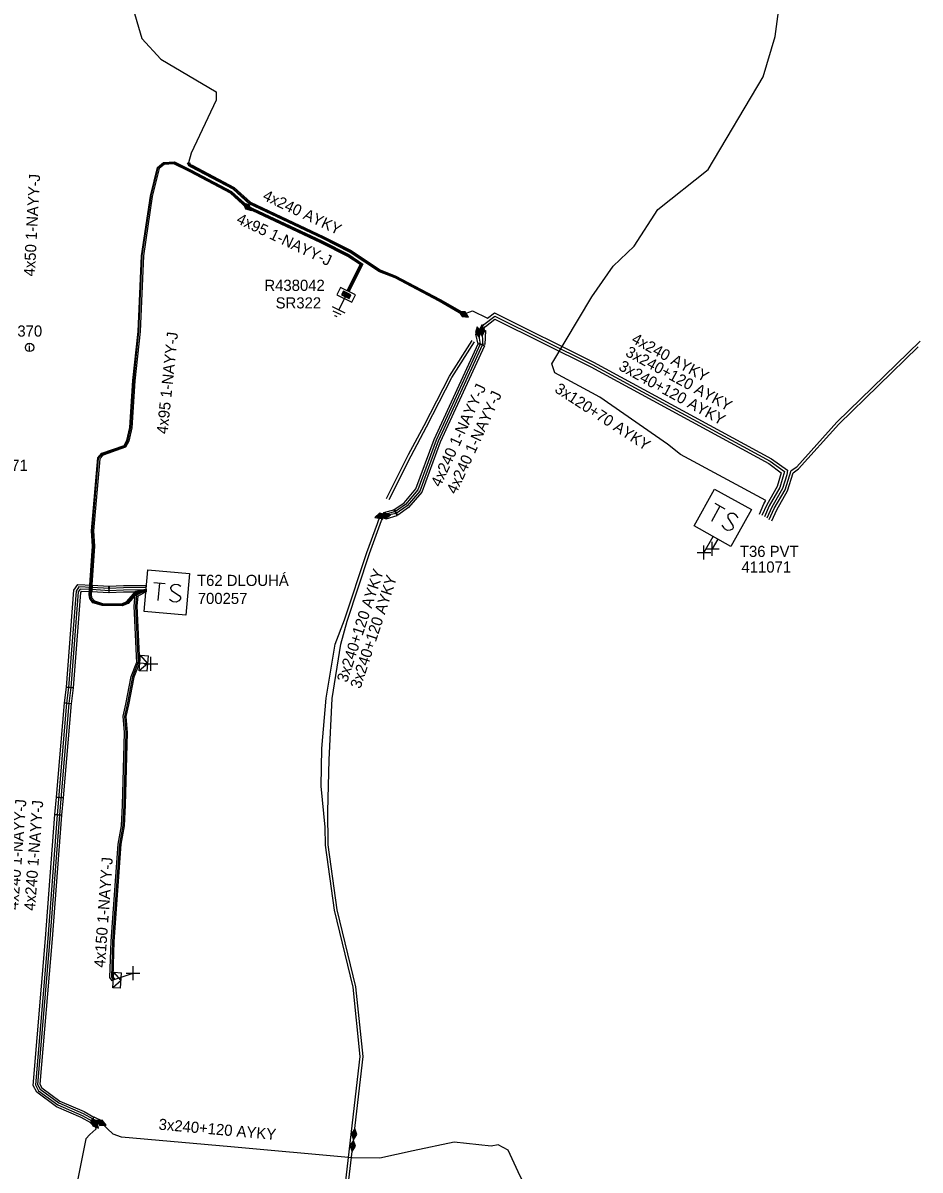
# Model space of a CAD drawing. Extents: x -540466 to -537383, y -1184038 to -1179972.
# Drawn here: x -537936.6 to -537856, y -1180822.8 to -1180719.7 of the extents above; entities that cross this region are included whole.
import ezdxf

# ---------------------------------------------------------------- set-up
doc = ezdxf.new("R2010")
doc.units = 0
for name, color, linetype in [('Vrstva 1', 7, 'Continuous'), ('Vrstva 10', 7, 'Continuous'), ('Vrstva 14', 7, 'Continuous'), ('Vrstva 15', 7, 'Continuous'), ('Vrstva 19', 7, 'Continuous'), ('Vrstva 20', 7, 'Continuous'), ('Vrstva 25', 7, 'Continuous'), ('Vrstva 26', 7, 'Continuous'), ('Vrstva 27', 7, 'Continuous'), ('Vrstva 28', 7, 'Continuous'), ('Vrstva 29', 7, 'Continuous'), ('Vrstva 30', 7, 'Continuous'), ('Vrstva 31', 7, 'Continuous'), ('Vrstva 34', 7, 'Continuous'), ('Vrstva 36', 7, 'Continuous'), ('Vrstva 4', 7, 'Continuous'), ('Vrstva 5', 7, 'Continuous'), ('Vrstva 59', 7, 'Continuous'), ('Vrstva 6', 7, 'Continuous'), ('Vrstva 8', 7, 'Continuous'), ('Vrstva 9', 7, 'Continuous')]:
    doc.layers.add(name, color=color, linetype=linetype)

# ---------------------------------------------------------------- blocks, each defined once
blk = doc.blocks.new('NN770')
at = {"layer": 'Vrstva 10'}
for p, q in [((0, 0.19), (0, 0.26)), ((0, -0.28), (0, 0.11))]:
    blk.add_line(p, q, dxfattribs=at)
blk.add_circle((0, -0.01), 0.375, dxfattribs=at)
blk = doc.blocks.new('NN870')
at = {"layer": 'Vrstva 4'}
for points in [[(0, -0.25), (0.5, 0), (0, 0.25), (-0.5, 0), (0, -0.25)], [(0.37, 0), (0, 0.19), (-0.36, 0), (0, -0.19), (0.37, 0)], [(0.24, 0), (0, 0.12), (-0.25, 0), (0, -0.12), (0.24, 0)], [(0.12, 0), (0, 0.06), (-0.13, 0), (0, -0.06), (0.12, 0)]]:
    blk.add_lwpolyline(points, dxfattribs=at)
blk = doc.blocks.new('NN800')
at = {"layer": 'Vrstva 1'}
for points in [[(-0.44, 0.44), (0.44, -0.44)], [(-0.44, -0.44), (0.44, 0.44)]]:
    blk.add_lwpolyline(points, dxfattribs=at)
blk = doc.blocks.new('NN620')
at = {"layer": 'Vrstva 8'}
for points in [[(0.75, 0), (-0.75, 0)], [(-0.75, 0), (-0.75, -0.75)], [(0.75, -0.75), (0.75, 0)], [(-0.75, -0.75), (0.75, -0.75)], [(0.37, -0.18), (-0.38, -0.18)], [(-0.38, -0.18), (-0.38, -0.56)], [(-0.38, -0.56), (0.37, -0.56)], [(0.32, -0.23), (-0.33, -0.23)], [(-0.33, -0.23), (-0.33, -0.51)], [(-0.33, -0.51), (0.32, -0.51)], [(0.27, -0.27), (-0.28, -0.27)], [(-0.28, -0.27), (-0.28, -0.46)], [(-0.28, -0.46), (0.27, -0.46)], [(0.23, -0.32), (-0.23, -0.32)], [(-0.23, -0.32), (-0.23, -0.42)], [(-0.23, -0.42), (0.23, -0.42)], [(-0.19, -0.37), (0.19, -0.37)], [(0.23, -0.42), (0.23, -0.32)], [(0.27, -0.46), (0.27, -0.27)], [(0.32, -0.51), (0.32, -0.23)], [(0.37, -0.56), (0.37, -0.18)]]:
    blk.add_lwpolyline(points, dxfattribs=at)
blk = doc.blocks.new('NN630')
at = {"layer": 'Vrstva 9'}
for points in [[(0, -0.7), (-0.7, 0)], [(-0.7, -0.7), (-0.7, 0), (0.7, 0), (0.7, -0.7)], [(-0.7, -0.7), (0.7, -0.7)], [(0, -0.7), (0.7, 0)]]:
    blk.add_lwpolyline(points, dxfattribs=at)
blk = doc.blocks.new('NN810')
at = {"layer": 'Vrstva 14'}
for points in [[(0, -0.64), (0, -1.89)], [(0.63, -1.89), (-0.62, -1.89)], [(0.39, -2.2), (-0.4, -2.2)], [(0, -2.52), (-0.12, -2.52)], [(0.14, -2.52), (0, -2.52)]]:
    blk.add_lwpolyline(points, dxfattribs=at)
blk = doc.blocks.new('NN640')
at = {"layer": 'Vrstva 6'}
for points in [[(-1.89, 1.89), (1.89, 1.89)], [(-1.89, -1.89), (-1.89, 1.89)], [(1.89, 1.89), (1.89, -1.89)], [(-1.26, 0.79), (-0.22, 0.79)], [(-0.73, 0.79), (-0.73, -0.79)], [(1.2, 0.66), (0.94, 0.79), (0.66, 0.79), (0.41, 0.66), (0.28, 0.47), (0.28, 0.41), (0.41, 0.22), (1.13, -0.16), (1.26, -0.32), (1.26, -0.47), (1.13, -0.66), (0.91, -0.79), (0.63, -0.79), (0.5, -0.73), (0.28, -0.6)], [(1.89, -1.89), (-1.89, -1.89)]]:
    blk.add_lwpolyline(points, dxfattribs=at)

msp = doc.modelspace()

# ---------------------------------------------------------------- linework, layer by layer
at = {"layer": 'Vrstva 20'}
for points in [[(-537925.96, -1180740.62), (-537925.15, -1180735.25), (-537924.51, -1180732.69), (-537923.97, -1180732.24), (-537922.99, -1180732.18), (-537921.66, -1180732.83), (-537921.74, -1180733), (-537923.03, -1180732.36), (-537923.9, -1180732.41), (-537924.35, -1180732.79), (-537924.98, -1180735.29), (-537925.78, -1180740.64), (-537926.08, -1180747.43), (-537926.54, -1180751.86), (-537926.82, -1180756.08), (-537927.09, -1180757.29), (-537927.4, -1180757.82), (-537927.52, -1180757.67), (-537927.26, -1180757.22), (-537927, -1180756.06), (-537926.72, -1180751.85), (-537926.26, -1180747.42)], [(-537921.4, -1180732.49), (-537917.62, -1180734.5), (-537916.16, -1180735.8), (-537909.56, -1180738.91), (-537907.11, -1180740.16), (-537904.48, -1180741.9), (-537903.07, -1180742.46), (-537899.09, -1180744.55), (-537896.94, -1180745.79), (-537897.03, -1180745.95), (-537899.18, -1180744.71), (-537903.15, -1180742.62), (-537904.56, -1180742.06), (-537907.2, -1180740.32), (-537909.64, -1180739.07), (-537916.26, -1180735.95), (-537917.72, -1180734.65), (-537921.48, -1180732.65), (-537921.7, -1180732.55), (-537921.81, -1180732.3), (-537921.63, -1180732.24), (-537921.56, -1180732.42)], [(-537921.74, -1180733), (-537921.66, -1180732.83), (-537921.55, -1180732.89), (-537921.49, -1180732.92), (-537917.86, -1180734.85), (-537916.4, -1180736.15), (-537909.74, -1180739.29), (-537907.32, -1180740.52), (-537906.04, -1180741.37), (-537906.29, -1180741.42), (-537907.41, -1180740.68), (-537909.82, -1180739.45), (-537916.5, -1180736.3), (-537917.96, -1180735), (-537921.58, -1180733.08)], [(-537907.29, -1180743.84), (-537907.47, -1180743.76), (-537906.29, -1180741.42), (-537906.04, -1180741.37)], [(-537895.03, -1180747.35), (-537895.09, -1180748.6), (-537895.69, -1180748.58), (-537895.89, -1180747.67), (-537895.53, -1180747.33)], [(-537895.12, -1180748.72), (-537899.09, -1180757.39), (-537900.76, -1180761.88), (-537901.94, -1180763.27), (-537902.91, -1180763.96), (-537903.25, -1180763.48), (-537902.34, -1180762.83), (-537901.28, -1180761.58), (-537899.64, -1180757.14), (-537895.66, -1180748.47)], [(-537927.4, -1180757.82), (-537929.41, -1180758.54), (-537929.51, -1180758.38), (-537927.52, -1180757.67)], [(-537929.71, -1180758.88), (-537930.25, -1180765.36), (-537930.17, -1180766.74), (-537930.47, -1180771.09), (-537930.43, -1180771.36), (-537930.19, -1180771.65), (-537930.31, -1180771.83), (-537930.6, -1180771.43), (-537930.65, -1180771.1), (-537930.35, -1180766.74), (-537930.43, -1180765.36), (-537929.88, -1180758.8), (-537929.51, -1180758.38), (-537929.41, -1180758.54)], [(-537903.97, -1180764.3), (-537904.15, -1180763.72), (-537903.17, -1180763.43), (-537902.99, -1180764.01)], [(-537932.1, -1180779.46), (-537932.7, -1180779.42), (-537932.02, -1180770.7), (-537931.67, -1180770.18), (-537930.39, -1180770.24), (-537930.41, -1180770.84), (-537931.37, -1180770.8), (-537931.44, -1180770.9)], [(-537930.42, -1180770.84), (-537930.38, -1180770.24), (-537928.85, -1180770.34), (-537928.89, -1180770.94)], [(-537929.49, -1180772.08), (-537929.45, -1180771.88), (-537927.73, -1180771.91), (-537927.28, -1180771.72), (-537926.45, -1180770.77), (-537925.59, -1180770.6), (-537925.54, -1180770.6), (-537925.54, -1180770.8), (-537925.57, -1180770.8), (-537926.35, -1180770.95), (-537927.16, -1180771.88), (-537927.69, -1180772.11)], [(-537925.57, -1180770.86), (-537927.56, -1180770.88), (-537928.86, -1180770.94), (-537928.88, -1180770.34), (-537927.57, -1180770.28), (-537925.57, -1180770.26)], [(-537926.14, -1180777.21), (-537926.38, -1180777.22), (-537926.61, -1180772.12), (-537926.53, -1180771.07), (-537925.65, -1180770.63), (-537925.53, -1180770.85), (-537926.29, -1180771.23), (-537926.37, -1180772.11)], [(-537929.45, -1180771.88), (-537929.49, -1180772.08), (-537930.31, -1180771.83), (-537930.19, -1180771.65)], [(-537927.48, -1180783.49), (-537927.61, -1180782.03), (-537927.36, -1180780.95), (-537926.88, -1180778.44), (-537926.38, -1180777.16), (-537926.14, -1180777.26), (-537926.64, -1180778.51), (-537927.12, -1180781), (-537927.35, -1180782.05), (-537927.24, -1180783.5), (-537927.42, -1180790.03), (-537927.51, -1180791.87), (-537927.8, -1180793.54), (-537928.43, -1180802.27), (-537928.53, -1180805.44), (-537928.39, -1180805.66), (-537928.59, -1180805.8), (-537928.79, -1180805.52), (-537928.68, -1180802.25), (-537928.04, -1180793.52), (-537927.76, -1180791.87), (-537927.67, -1180790.02)], [(-537932.28, -1180780.9), (-537932.88, -1180780.82), (-537932.7, -1180779.4), (-537932.1, -1180779.48)], [(-537932.28, -1180780.89), (-537933, -1180789.36), (-537933.6, -1180789.3), (-537932.88, -1180780.83)], [(-537933, -1180789.35), (-537933.13, -1180790.92), (-537933.73, -1180790.86), (-537933.6, -1180789.3)], [(-537933.13, -1180790.91), (-537933.98, -1180802.04), (-537935.08, -1180815.09), (-537934.91, -1180815.42), (-537933.28, -1180816.62), (-537931.11, -1180817.57), (-537930.22, -1180818.06), (-537930.5, -1180818.58), (-537931.37, -1180818.11), (-537933.58, -1180817.14), (-537935.37, -1180815.82), (-537935.7, -1180815.21), (-537934.58, -1180802), (-537933.73, -1180790.87)], [(-537930.26, -1180818.27), (-537930, -1180818.55), (-537930.3, -1180818.82), (-537930.56, -1180818.54)], [(-537930.23, -1180818.05), (-537929.49, -1180818.4), (-537929.67, -1180818.76), (-537930.4, -1180818.41)]]:
    msp.add_lwpolyline(points, close=True, dxfattribs=at)
at = {"layer": 'Vrstva 5'}
for points in [[(-537909.44, -1180691.29), (-537909.99, -1180690.74), (-537911.8, -1180691.54), (-537913.18, -1180691.42), (-537926.87, -1180717.83), (-537925.93, -1180721.09), (-537924.2, -1180722.94), (-537919.24, -1180725.87), (-537919.25, -1180726.62), (-537921.48, -1180731.4), (-537921.72, -1180732.27)], [(-537870.4, -1180763.87), (-537870.01, -1180762.94), (-537869.81, -1180762.63), (-537877.5, -1180758.48), (-537878.66, -1180757.56), (-537884.73, -1180753.35), (-537888.8, -1180751.14), (-537889.07, -1180750.34), (-537885.47, -1180744.32), (-537883.54, -1180741.56), (-537881.65, -1180739.76), (-537879.52, -1180736.45), (-537875.01, -1180732.88), (-537870.07, -1180724.55), (-537868.97, -1180720.91), (-537868.31, -1180715.92), (-537866.59, -1180712.23), (-537867.39, -1180711.83)], [(-537925.54, -1180770.7), (-537925.58, -1180770.7), (-537926.4, -1180770.86), (-537927.22, -1180771.8), (-537927.71, -1180772.01), (-537929.47, -1180771.98), (-537930.25, -1180771.74), (-537930.53, -1180771.4), (-537930.57, -1180771.09), (-537930.27, -1180766.74), (-537930.35, -1180765.36), (-537929.81, -1180758.83), (-537929.46, -1180758.45), (-537927.46, -1180757.73), (-537927.18, -1180757.25), (-537926.92, -1180756.07), (-537926.64, -1180751.86), (-537926.18, -1180747.43), (-537925.88, -1180740.63), (-537925.07, -1180735.27), (-537924.44, -1180732.73), (-537923.94, -1180732.32), (-537923.01, -1180732.26), (-537921.7, -1180732.91), (-537921.53, -1180732.99), (-537917.91, -1180734.92), (-537916.44, -1180736.22), (-537909.78, -1180739.36), (-537907.36, -1180740.59), (-537906.16, -1180741.39), (-537907.38, -1180743.8)], [(-537921.72, -1180732.27), (-537921.64, -1180732.49), (-537921.45, -1180732.58), (-537917.68, -1180734.58), (-537916.22, -1180735.88), (-537909.6, -1180739), (-537907.16, -1180740.25), (-537905.96, -1180741.04), (-537904.53, -1180741.99), (-537903.12, -1180742.55), (-537899.14, -1180744.64), (-537896.99, -1180745.88)], [(-537896.99, -1180745.88), (-537896.19, -1180745.58), (-537894.84, -1180746.24), (-537894.21, -1180745.76), (-537885.31, -1180750.18), (-537869.3, -1180758.88), (-537867.88, -1180759.91), (-537867.93, -1180760.31), (-537868.31, -1180761.55), (-537869.29, -1180763.24), (-537869.73, -1180764.21)], [(-537895.69, -1180747.49), (-537895.17, -1180746.79), (-537894.18, -1180746.06), (-537885.42, -1180750.4), (-537869.43, -1180759.09), (-537868.15, -1180760.02), (-537868.55, -1180761.47), (-537869.51, -1180763.12), (-537869.95, -1180764.1)], [(-537895.33, -1180747.34), (-537895.02, -1180746.99), (-537894.17, -1180746.33), (-537885.54, -1180750.62), (-537869.56, -1180759.3), (-537868.43, -1180760.13), (-537868.79, -1180761.38), (-537869.73, -1180763.01), (-537870.18, -1180763.99)], [(-537895.69, -1180747.49), (-537895.49, -1180748.57), (-537899.45, -1180757.21), (-537901.11, -1180761.68), (-537902.21, -1180762.98), (-537903.12, -1180763.63), (-537904.48, -1180764.01)], [(-537895.33, -1180747.34), (-537895.29, -1180748.61), (-537899.27, -1180757.29), (-537900.93, -1180761.78), (-537902.07, -1180763.12), (-537903.04, -1180763.81), (-537904.06, -1180764.01)], [(-537869.51, -1180764.34), (-537869.07, -1180763.35), (-537868.09, -1180761.66), (-537867.55, -1180759.94), (-537867.04, -1180759.59), (-537863.44, -1180755.58), (-537855.95, -1180748.29)], [(-537869.29, -1180764.46), (-537868.84, -1180763.47), (-537867.86, -1180761.77), (-537867.36, -1180760.14), (-537866.88, -1180759.77), (-537863.26, -1180755.76), (-537856.13, -1180748.81)], [(-537906.94, -1180839.06), (-537906.96, -1180839.24), (-537908.39, -1180839.21), (-537908.83, -1180838.57), (-537908.99, -1180837.21), (-537908.41, -1180831.05), (-537906.28, -1180812.62), (-537906.91, -1180806.39), (-537908.6, -1180799.46), (-537909.42, -1180793.61), (-537909.45, -1180792), (-537909.81, -1180788.32), (-537909.74, -1180784.93), (-537909.34, -1180780.41), (-537908.54, -1180775.53), (-537907.69, -1180773.37), (-537905.7, -1180767.31), (-537904.74, -1180764.7), (-537904.48, -1180764.01)], [(-537906.83, -1180819.6), (-537906.02, -1180812.62), (-537906.67, -1180806.35), (-537908.36, -1180799.42), (-537909.18, -1180793.58), (-537909.18, -1180793.5), (-537909.21, -1180790.59), (-537909.07, -1180785.93), (-537908.8, -1180780.42), (-537908.04, -1180775.55), (-537907.47, -1180773.48), (-537905.46, -1180767.39), (-537904.38, -1180764.44), (-537904.06, -1180764.01)], [(-537925.54, -1180770.46), (-537927.56, -1180770.48), (-537928.87, -1180770.54), (-537930.4, -1180770.44), (-537931.57, -1180770.39), (-537931.83, -1180770.77), (-537932.5, -1180779.43), (-537932.68, -1180780.85), (-537933.53, -1180790.88), (-537934.38, -1180802.01), (-537935.49, -1180815.17), (-537935.22, -1180815.69), (-537933.48, -1180816.97), (-537931.28, -1180817.93), (-537930.41, -1180818.41), (-537930.15, -1180818.69)], [(-537925.56, -1180770.66), (-537927.56, -1180770.68), (-537928.87, -1180770.74), (-537930.41, -1180770.64), (-537931.47, -1180770.59), (-537931.63, -1180770.83), (-537932.3, -1180779.45), (-537932.48, -1180780.87), (-537933.33, -1180790.9), (-537934.18, -1180802.03), (-537935.29, -1180815.13), (-537935.06, -1180815.55), (-537933.38, -1180816.79), (-537931.2, -1180817.75), (-537930.31, -1180818.23), (-537929.58, -1180818.58)], [(-537925.55, -1180770.8), (-537925.69, -1180770.79), (-537926.41, -1180771.15), (-537926.49, -1180772.12), (-537926.28, -1180776.63), (-537926.26, -1180777.12), (-537926.09, -1180777.23), (-537926.3, -1180777.3), (-537926.76, -1180778.47), (-537927.24, -1180780.97), (-537927.48, -1180782.04), (-537927.36, -1180783.49), (-537927.54, -1180790.02), (-537927.63, -1180791.86), (-537927.92, -1180793.53), (-537928.55, -1180802.26), (-537928.66, -1180805.48), (-537928.49, -1180805.73)], [(-537930.15, -1180818.69), (-537930.05, -1180819.14), (-537930.58, -1180819.63), (-537930.95, -1180820.02), (-537932.42, -1180827.35), (-537933.21, -1180834.74), (-537934.78, -1180846.97), (-537934.83, -1180851.11)], [(-537887.63, -1180830.78), (-537887.78, -1180830.85), (-537888.19, -1180830.28), (-537891.92, -1180823.36), (-537892.98, -1180821.05), (-537893.87, -1180820.57), (-537894.51, -1180820.69), (-537897.84, -1180820.33), (-537901.53, -1180821.1), (-537904.52, -1180821.77), (-537907, -1180821.74), (-537917.93, -1180820.75), (-537927.76, -1180819.88), (-537928.5, -1180819.6), (-537929.58, -1180818.58)], [(-537906.96, -1180820.65), (-537906.83, -1180819.6)], [(-537907.31, -1180839.02), (-537908.25, -1180838.97), (-537908.59, -1180838.48), (-537908.73, -1180837.21), (-537908.17, -1180831.07), (-537906.96, -1180820.65)]]:
    msp.add_lwpolyline(points, dxfattribs=at)
at = {"layer": 'Vrstva 59'}
for points in [[(-537874.59, -1180765.88), (-537875.38, -1180767.3)], [(-537874.14, -1180766.09), (-537874.63, -1180766.97)], [(-537926.09, -1180777.23), (-537925.1, -1180777.31)], [(-537928.49, -1180805.73), (-537926.71, -1180805.12)]]:
    msp.add_lwpolyline(points, dxfattribs=at)
at = {"layer": 'Vrstva 9'}
for points in [[(-537903.92, -1180762.45), (-537901.93, -1180758.5), (-537900.55, -1180755.89), (-537898.26, -1180751.45), (-537896.22, -1180748.24)], [(-537903.69, -1180762.55), (-537901.71, -1180758.62), (-537900.33, -1180756.01), (-537898.04, -1180751.57), (-537896, -1180748.36)]]:
    msp.add_lwpolyline(points, dxfattribs=at)

# ---------------------------------------------------------------- block references
at = {"layer": 'Vrstva 15', "rotation": -26.053494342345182}
msp.add_blockref('NN810', (-537907.38, -1180743.8), dxfattribs=at)
at = {"layer": 'Vrstva 19'}
for p, rotation in [((-537916.44, -1180736.22), -41.665147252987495), ((-537896.99, -1180745.88), -30.058124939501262), ((-537895.69, -1180747.49), -79.41893053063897), ((-537895.33, -1180747.34), -88.24659442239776), ((-537904.48, -1180764.01), 15.693952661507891), ((-537904.06, -1180764.01), 10.997549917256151), ((-537930.15, -1180818.69), -47.54480551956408), ((-537929.58, -1180818.58), -25.42687499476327), ((-537906.83, -1180819.6), 83.37845826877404), ((-537906.96, -1180820.65), 83.37845833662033)]:
    msp.add_blockref('NN870', p, dxfattribs=dict(at, rotation=rotation))
at = {"layer": 'Vrstva 25'}
for p, rotation in [((-537873.69, -1180764.18), -28.95763339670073), ((-537923.67, -1180770.9), -5.050661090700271)]:
    msp.add_blockref('NN640', p, dxfattribs=dict(at, rotation=rotation))
at = {"layer": 'Vrstva 28', "rotation": -26.053494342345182}
msp.add_blockref('NN620', (-537907.38, -1180743.8), dxfattribs=at)
at = {"layer": 'Vrstva 31'}
for p, rotation in [((-537926.09, -1180777.23), 85.18725832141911), ((-537928.49, -1180805.73), 85.86427216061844)]:
    msp.add_blockref('NN630', p, dxfattribs=dict(at, rotation=rotation))
at = {"layer": 'Vrstva 34'}
for p, rotation in [((-537875.38, -1180767.3), 44.99999995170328), ((-537874.63, -1180766.97), 45), ((-537925.1, -1180777.31), 45), ((-537926.71, -1180805.12), 45)]:
    msp.add_blockref('NN800', p, dxfattribs=dict(at, rotation=rotation))
at = {"layer": 'Vrstva 36'}
msp.add_blockref('NN770', (-537936.01, -1180748.86), dxfattribs=at)

# ---------------------------------------------------------------- texts
at = {"layer": 'Vrstva 14'}
for s, p in [('370', (-537937.11, -1180747.89)), ('371', (-537938.4, -1180759.96))]:
    msp.add_text(s, height=1, dxfattribs=at).set_placement(p)
at = {"layer": 'Vrstva 26'}
for s, p in [('411071', (-537872.01, -1180769.11)), ('700257', (-537920.89, -1180771.93))]:
    msp.add_text(s, height=1, dxfattribs=at).set_placement(p)
at = {"layer": 'Vrstva 27'}
for s, p in [('T36 PVT', (-537872.15, -1180767.7)), ('T62 DLOUHÁ', (-537920.96, -1180770.31))]:
    msp.add_text(s, height=1, dxfattribs=at).set_placement(p)
at = {"layer": 'Vrstva 29'}
msp.add_text('R438042', height=1, dxfattribs=at).set_placement((-537914.9, -1180743.78))
at = {"layer": 'Vrstva 30'}
msp.add_text('SR322', height=1, dxfattribs=at).set_placement((-537913.89, -1180745.36))
at = {"layer": 'Vrstva 6'}
for s, rotation, p in [('4x50 1-NAYY-J', 86.914, (-537935.55, -1180742.5)), ('4x240 AYKY', 334.763, (-537915.13, -1180735.55)), ('4x95 1-NAYY-J', 334.76, (-537917.49, -1180737.65)), ('4x95 1-NAYY-J', 84.062, (-537923.61, -1180756.69)), ('4x240 AYKY', 331.478, (-537881.97, -1180748.39)), ('3x240+120 AYKY', 331.477, (-537882.52, -1180749.57)), ('3x240+120 AYKY', 331.477, (-537883.13, -1180750.84)), ('4x240 1-NAYY-J', 65.375, (-537899.08, -1180761.49)), ('3x120+70 AYKY', 326.986, (-537888.88, -1180752.82)), ('4x240 1-NAYY-J', 65.369, (-537897.67, -1180762.13)), ('3x240+120 AYKY', 71.77, (-537907.47, -1180779.05)), ('3x240+120 AYKY', 71.794, (-537906.27, -1180779.61)), ('4x240 1-NAYY-J', 85.633, (-537937.05, -1180799.45)), ('4x240 1-NAYY-J', 85.633, (-537935.53, -1180799.54)), ('4x150 1-NAYY-J', 85.872, (-537929.24, -1180804.66)), ('3x240+120 AYKY', 354.941, (-537924.44, -1180819.19))]:
    msp.add_text(s, height=1, rotation=rotation, dxfattribs=at).set_placement(p)

doc.saveas('drawing.dxf')
